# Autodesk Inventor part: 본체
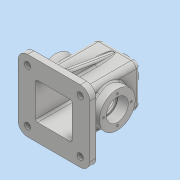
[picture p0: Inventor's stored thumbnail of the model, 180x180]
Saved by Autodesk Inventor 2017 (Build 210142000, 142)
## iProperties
Part Number: 본체
Material: 일반
Document SubType Name: Modeling
Designer: MRC
Density: 1 g/cm^3
Appearance: 기본값
Author: MRC
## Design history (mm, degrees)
sketch "스케치2"
  geometry: L1 (-34, -52.5)-(34, -52.5); L2 (34, -52.5)-(34, 52.5); L3 (34, 52.5)-(-34, 52.5); L4 (-34, 52.5)-(-34, -52.5); L5 (-34, -52.5)-(34, 52.5); L6 (34, -52.5)-(-34, 52.5); 1 further point
  constraints: 12 end point, 2 midpoint, 2 parallel, 1 horizontal, 1 perpendicular
  dimensions: "d0" = 68 distance of L2.end L3.end; "d1" = 105 distance of L1.end L2.end
extrude "돌출1" new body sketch "스케치2" stored distance "d2" = 68; taper "d3" = 0 deg
sketch "스케치4"
  geometry: L1 (68, 0)-(0, 0) reference; L2 (0, 105)-(68, 105) reference; C1 r 28.5 at (34, 52); 2 further points
  constraints: 1 centre point, 1 coincident, 1 midpoint, 1 vertical alignment
  dimensions: "d5" = 57 diameter of C1; "d103" = 52 distance from line of L1 point (34, 52)
extrude "돌출2" join sketch "스케치4" distance "d6" = 15; taper "d7" = 0 deg
sketch "스케치5"
  geometry: L1 (68, 0)-(0, 0) reference; L2 (68, 105)-(0, 105) reference; C1 r 28.5 at (34, 52); 2 further points
  constraints: 1 centre point, 1 coincident, 1 midpoint, 1 vertical alignment
  dimensions: "d8" = 57 diameter of C1; "d104" = 52 distance from line of L1 point (34, 52)
extrude "돌출3" join sketch "스케치5" distance "d9" = 15; taper "d10" = 0 deg
sketch "스케치6"
  geometry: L1 (5, -63)-(63, -63); L2 (63, -63)-(63, -5); L3 (63, -5)-(5, -5); L4 (5, -5)-(5, -63); L5 (5, -63)-(63, -5); L6 (63, -63)-(5, -5); 1 further point
  constraints: 12 end point, 2 midpoint, 2 parallel, 1 horizontal, 1 perpendicular
  dimensions: "d11" = 58 distance of L3.end L2.end; "d12" = 58 distance of L2.end L1.end
extrude "돌출4" cut sketch "스케치6" distance "d13" = 100; taper "d14" = 0 deg
sketch "스케치7"
  geometry: C1 r 28.5 at (0, 0) reference; 2 further points
  constraints: 1 coincident
hole "구멍1" sketch "스케치7" at (0, 0) diameter "d15" = 30; stored, may be unused: countersink angle "d19" = 90 deg, drill point angle "d21" = 0 deg; dims "d16" = 6, "d17" = 35, "d18" = 17, "d20" = 40
sketch "스케치8"
  geometry: C1 r 28.5 at (0, 0) reference; 2 further points
  constraints: 1 vertical alignment
  dimensions: "d105" = 22 distance of C1.centre point (0, 22)
hole "구멍2" sketch "스케치8" diameter "d23" = 3.242; stored, may be unused: countersink angle "d27" = 90 deg, drill point angle "d29" = 118 deg; dims "d24" = 8, "d25" = 35, "d26" = 17, "d28" = 10
sketch "스케치11"
  geometry: L1 (68, -68)-(68, 0) reference; L2 (68, -68)-(0, -68) reference; L3 (0, 0)-(0, -68) reference; L4 (0, 0)-(68, 0) reference; L5 (91, 23)-(91, -91); L6 (91, -91)-(-23, -91); L7 (-23, -91)-(-23, 23); L8 (-23, 23)-(91, 23); 1 further point
  constraints: 8 end point, 3 other
  dimensions: "d33" = 23 distance between parallel lines of L1 L5
extrude "돌출6" join sketch "스케치11" distance "d49" = 10; taper "d50" = 0 deg
sketch "스케치14"
  geometry: 5 further points
  constraints: 2 horizontal alignment, 2 vertical alignment
  dimensions: "d51" = 84 distance of point (-8, -8) point (76, -8); "d52" = 42 horizontal distance of point (34, 34) point (76, -8); "d53" = 42 horizontal distance of point (76, -8) point (34, 34); "d54" = 84 distance of point (76, -8) point (76, 76)
hole "구멍4" sketch "스케치14" at (76, -8), (-8, -8), (-8, 76), (76, 76) diameter "d55" = 10; stored, may be unused: countersink angle "d59" = 90 deg, drill point angle "d61" = 0 deg; dims "d56" = 8, "d57" = 18, "d58" = 2, "d60" = 10
fillet "모깎기2" dims "d62" = 15
node "작업 평면1"
node "작업 평면2"
sketch "스케치18"
  geometry: C1 r 20 at (42, 57); 1 further point
  constraints: 1 centre point, 1 coincident
  dimensions: "d66" = 40 diameter of C1
extrude "돌출7" join sketch "스케치18" distance "d67" = 10; taper "d68" = 0 deg
sketch "스케치19"
  geometry: 1 further point
hole "구멍5" sketch "스케치19" at (0, 0) diameter "d69" = 22.835; stored, may be unused: countersink angle "d73" = 90 deg, drill point angle "d75" = 0 deg; dims "d70" = 40, "d71" = 18, "d72" = 2, "d74" = 40
chamfer "모따기2" distance "d79" = 1; stored, may be unused: second distance "d80" = 2, angle "d81" = 45 deg
sketch "스케치21"
  geometry: L1 (52.5, -34)-(-42.5, -34) reference; L2 (-42.5, -33)-(-42.5, -51) reference; L3 (-42.5, 34)-(52.5, 34) reference; L4 (-42.5, 51)-(-42.5, 33) reference; L5 (42.569, 34)-(-42.5, 49); L6 (-42.5, -42)-(-42.5, -57) reference; L7 (-42.5, 57)-(-52.5, 57) reference; 3 further points
  constraints: 2 end point, 2 point on line
  dimensions: "d82" = 100 deg angle of L5 L4; "d84" = 8 distance from line of L7 L5.end
feature "리브1" sketch "스케치21" dims "d85" = 1, "d86" = 10, "d87" = 0, "d88" = 0, "d89" = 1, "d90" = 1
fillet "모깎기3" dims "d91" = 8
fillet "모깎기4" dims "d92" = 8
fillet "모깎기5" dims "d93" = 3
fillet "모깎기6" dims "d94" = 3
fillet "모깎기7" dims "d95" = 3
fillet "모깎기8" dims "d96" = 3
feature "면 기울기1" dims angle "d97" = 8 deg
sketch "스케치22"
  geometry: L1 (-8, 0)-(-8, -84) reference; L2 (46, 18)-(6, 18) reference; 2 further points
  constraints: 1 other
  dimensions: "d98" = 34 distance from line of L1 point (26, -7); "d99" = 25 distance from line of L2 point (26, -7)
feature "엠보싱1" sketch "스케치22" dims "d100" = 0.5, "d101" = 0
fillet "모깎기9" dims "d102" = 3
fillet "모깎기10" dims "d109" = 0.3
node "솔리드1"
mirror "미러2"
pattern_circular "원형 패턴2" dims angle "d107" = 360 deg
mirror "미러3"
mirror "미러4"
other parameters: "d63" = -115, "d65" = -115
